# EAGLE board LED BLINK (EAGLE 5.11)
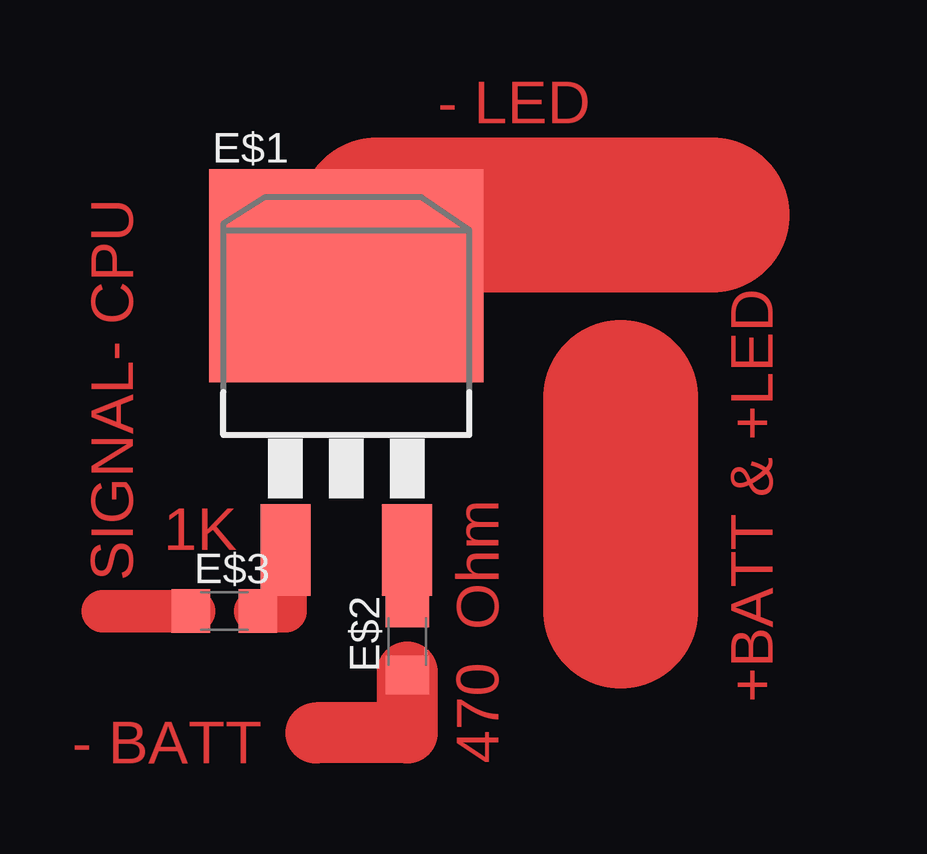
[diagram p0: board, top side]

No outline drawn. Coordinates in mm, seen from the top.
Copper layers (1*16): Top 0.035mm / dielectric 1.5mm / Bottom 0.035mm
Design rules "default": minimum track width 10mil, minimum drill 24mil, track to track 8mil, track to pad 8mil, pad to pad 8mil, via to via 8mil, smd to smd 8mil, copper to edge 40mil, drill to drill 8mil, minimum pad ring 10mil, minimum via ring 8mil, stop-mask expansion 4mil, vias tented up to drill 0mil, thermal gap 10mil

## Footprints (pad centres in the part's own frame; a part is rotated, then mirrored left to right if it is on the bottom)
D2PACK = smd 2.083 x 3.81: 1 -2.54,-8.89; 3 2.54,-8.89 | smd 11.43 x 8.89: 2 0,2.54
C1206 = smd 1.6 x 1.8: 1 -1.4,0; 2 1.4,0

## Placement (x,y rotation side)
E$1  [D2PACK]  11.43,17.78 0 top
E$2  [C1206]  13.97,5.08 90 top
E$3  [C1206]  6.35,6.35 0 top

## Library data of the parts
E$1 = transistor-fet
E$2 E$3 = resistor

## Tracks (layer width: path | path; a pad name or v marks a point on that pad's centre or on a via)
S$1
  Top 1.778: 7.62,6.35 8.89,6.35 8.89,7.62
S$2
  Top 2.54: 13.97,3.81 13.97,1.27 10.16,1.27
S$3
  Top 6.452: 12.7,22.86 26.67,22.86
S$4
  Top 6.452: 22.86,15.24 22.86,6.35
S$5
  Top 1.778: 5.08,6.35 1.27,6.35

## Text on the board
Top: - LED | 1K | SIGNAL- CPU | +BATT & +LED | - BATT | 470 Ohm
